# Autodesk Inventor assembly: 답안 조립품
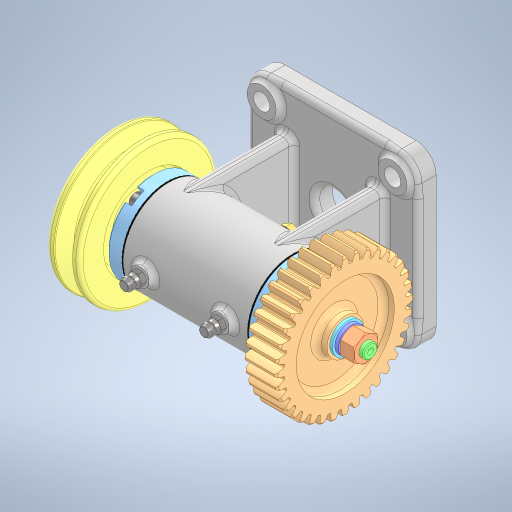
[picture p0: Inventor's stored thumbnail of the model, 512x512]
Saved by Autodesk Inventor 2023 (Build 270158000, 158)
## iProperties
Created: 2025-10
Part Number: 답안 조립품
Document SubType Name: Assembly
Designer: home
Author: home
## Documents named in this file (17)
- C:\Users\home\Desktop\751003V1010\답안 조립품.iam
- C:\Users\home\Desktop\751003V1010\본체.ipt
- C:\Users\home\Desktop\751003V1010\6각 구멍붙이 볼트 M4x10.ipt
- C:\Users\home\Desktop\751003V1010\6각 너트 M8x1.ipt
- C:\Users\home\Desktop\751003V1010\6각 머리 볼트 M6x0.75x8.ipt
- C:\Users\home\Desktop\751003V1010\V 벨트 풀리.ipt
- C:\Users\home\Desktop\751003V1010\가스켓.ipt
- C:\Users\home\Desktop\751003V1010\그리스 니플 M6x0.75.ipt
- C:\Users\home\Desktop\751003V1010\깊은 홈 볼 베어링 6002.ipt
- C:\Users\home\Desktop\751003V1010\스퍼 기어.ipt
- C:\Users\home\Desktop\751003V1010\스프링 와셔 M8.ipt
- C:\Users\home\Desktop\751003V1010\실링.ipt
- C:\Users\home\Desktop\751003V1010\오일 실 15 25 4.ipt
- C:\Users\home\Desktop\751003V1010\축.ipt
- C:\Users\home\Desktop\751003V1010\커버.ipt
- C:\Users\home\Desktop\751003V1010\평 와셔 M8.ipt
- C:\Users\home\Desktop\751003V1010\평행 키 3x3x12.ipt
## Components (14 placed, 6 different names)
1. 6각 구멍붙이 볼트 M4x10:1
2. 6각 너트 M8x1:1
3. 6각 머리 볼트 M6x0.75x8:1
4. V 벨트 풀리:1 — 각도:2
5. 가스켓:1
6. 그리스 니플 M6x0.75:1
7. 그리스 니플 M6x0.75:2
8. 6각 구멍붙이 볼트 M4x10:2
9. 6각 구멍붙이 볼트 M4x10:3
10. 6각 너트 M8x1:2
11. 가스켓:2
12. 6각 구멍붙이 볼트 M4x10:4
13. 6각 구멍붙이 볼트 M4x10:5
14. 6각 구멍붙이 볼트 M4x10:6
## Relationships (1: Angle 1)
- 각도:2 [Angle]: V 벨트 풀리:1
